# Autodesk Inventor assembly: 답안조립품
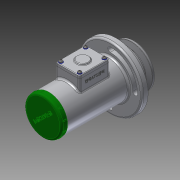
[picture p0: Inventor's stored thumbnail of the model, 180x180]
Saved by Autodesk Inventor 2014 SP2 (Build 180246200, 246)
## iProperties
Created: 2017-05
Part Number: 답안조립품
Document SubType Name: Assembly
Designer: 거성
Author: 거성
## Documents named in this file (20)
- C:\Users\거성\Desktop\470508V1018\답안조립품.iam
- C:\Users\거성\Desktop\470508V1018\본체.ipt
- C:\Users\거성\Desktop\470508V1018\탑 커버.ipt
- C:\Users\거성\Desktop\470508V1018\사이드 커버.ipt
- 사이드 커버.ipt
- C:\Users\거성\Desktop\470508V1018\베어링 15 x 35 x 11.ipt
- C:\Users\거성\Desktop\470508V1018\축.ipt
- C:\Users\거성\Desktop\470508V1018\오일 실 15 25 7.ipt
- C:\Users\거성\Desktop\470508V1018\부시1.ipt
- C:\Users\거성\Desktop\470508V1018\멈춤링 35x1.6.ipt
- C:\Users\거성\Desktop\470508V1018\멈춤링 15 x 1.ipt
- C:\Users\거성\Desktop\470508V1018\부시2.ipt
- C:\Users\거성\Desktop\470508V1018\와셔 10x21.ipt
- C:\Users\거성\Desktop\470508V1018\너트 M10.ipt
- C:\Users\거성\Desktop\470508V1018\키 4 x 4 x 18.ipt
- C:\Users\거성\Desktop\470508V1018\V-벨트풀리.ipt
- C:\Users\거성\Desktop\470508V1018\볼트 M4 x 10.ipt
- C:\Users\거성\Desktop\470508V1018\와셔 4x16.ipt
- C:\Users\거성\Desktop\470508V1018\십자볼트 M3 x 10.ipt
- C:\Users\거성\Desktop\470508V1018\와셔 3x6.ipt
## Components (2 placed, 2 different names)
1. V-벨트풀리:1 — 각도:3
2. ISO 4017 M4 x 10:1 — 각도:4
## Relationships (2: Angle 2)
- 각도:3 [Angle]: V-벨트풀리:1
- 각도:4 [Angle]: ISO 4017 M4 x 10:1
